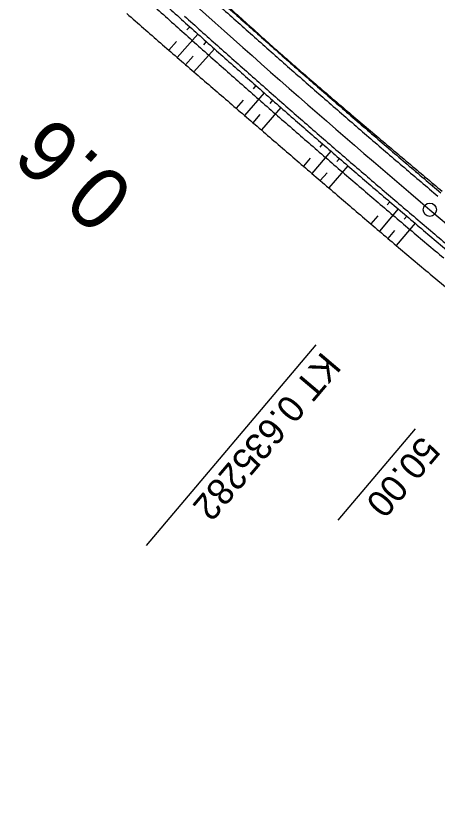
# Model space of a CAD drawing. Extents: x -481656 to -478728, y -1113199 to -1110710.
# Drawn here: x -481310.8 to -481263.1, y -1113096.8 to -1113006.1 of the extents above; entities that cross this region are included whole.
import ezdxf

# ---------------------------------------------------------------- set-up
doc = ezdxf.new("R2010")
doc.units = 0
for name, color, linetype in [('C11_HATCH_SLOPE_L', 7, 'Continuous'), ('C11_HATCH_SLOPE_R', 7, 'Continuous'), ('C11_HECTOMETRY', 7, 'Continuous'), ('C11_HLBODY', 7, 'Continuous'), ('C11_HRANA_TELESO', 7, 'Continuous'), ('C11_KORUNA', 7, 'Continuous'), ('C11_OSA', 7, 'Continuous'), ('C11_PRIKOP', 7, 'Continuous'), ('C11_STANICENI', 7, 'Continuous'), ('C11_VOZOVKA', 7, 'Continuous'), ('C11_ZPEVKRAJ', 7, 'Continuous')]:
    doc.layers.add(name, color=color, linetype=linetype)

msp = doc.modelspace()

# ---------------------------------------------------------------- linework, layer by layer
at = {"layer": 'C11_HATCH_SLOPE_L'}
for p, q in [((-481285.358, -1113006.444), (-481285.3, -1113006.378)), ((-481280.687, -1113010.579), (-481280.666, -1113010.555)), ((-481280.645, -1113010.531), (-481280.645, -1113010.531)), ((-481279.751, -1113011.403), (-481279.706, -1113011.353)), ((-481278.766, -1113012.173), (-481278.766, -1113012.173)), ((-481278.813, -1113012.226), (-481278.79, -1113012.2)), ((-481277.875, -1113013.049), (-481277.825, -1113012.992)), ((-481273.17, -1113017.145), (-481273.127, -1113017.096)), ((-481273.084, -1113017.046), (-481273.084, -1113017.046)), ((-481272.226, -1113017.962), (-481272.133, -1113017.854)), ((-481271.282, -1113018.777), (-481271.232, -1113018.718)), ((-481271.181, -1113018.66), (-481271.181, -1113018.66)), ((-481270.337, -1113019.591), (-481270.229, -1113019.466)), ((-481265.598, -1113023.648), (-481265.528, -1113023.565)), ((-481265.457, -1113023.482), (-481265.457, -1113023.482)), ((-481264.648, -1113024.457), (-481264.503, -1113024.286)), ((-481263.697, -1113025.264), (-481263.622, -1113025.176)), ((-481263.548, -1113025.089), (-481263.548, -1113025.089))]:
    msp.add_line(p, q, dxfattribs=at)
at = {"layer": 'C11_HATCH_SLOPE_R'}
for p, q in [((-481291.152, -1113007.302), (-481291.474, -1113007.662)), ((-481290.219, -1113008.138), (-481292.571, -1113010.769)), ((-481292.659, -1113008.984), (-481293.521, -1113009.947)), ((-481289.285, -1113008.972), (-481289.605, -1113009.331)), ((-481288.35, -1113009.805), (-481290.669, -1113012.41)), ((-481290.772, -1113010.64), (-481291.62, -1113011.59)), ((-481283.662, -1113013.956), (-481283.976, -1113014.312)), ((-481282.722, -1113014.783), (-481284.954, -1113017.322)), ((-481285.098, -1113015.586), (-481285.906, -1113016.503)), ((-481281.78, -1113015.609), (-481282.092, -1113015.965)), ((-481280.839, -1113016.435), (-481283.047, -1113018.958)), ((-481283.203, -1113017.231), (-481284.001, -1113018.141)), ((-481276.116, -1113020.547), (-481276.422, -1113020.9)), ((-481275.169, -1113021.366), (-481277.335, -1113023.872)), ((-481277.509, -1113022.154), (-481278.288, -1113023.055)), ((-481273.272, -1113023.002), (-481275.424, -1113025.502)), ((-481274.221, -1113022.184), (-481274.526, -1113022.537)), ((-481275.605, -1113023.788), (-481276.38, -1113024.687)), ((-481268.516, -1113027.074), (-481268.814, -1113027.424)), ((-481267.562, -1113027.886), (-481269.698, -1113030.399)), ((-481269.884, -1113028.68), (-481270.654, -1113029.585)), ((-481266.607, -1113028.696), (-481266.904, -1113029.046)), ((-481267.97, -1113030.304), (-481268.741, -1113031.212)), ((-481265.652, -1113029.506), (-481267.783, -1113032.025))]:
    msp.add_line(p, q, dxfattribs=at)
at = {"layer": 'C11_HLBODY'}
msp.add_line((-481276.899, -1113043.241), (-481296.08, -1113065.916), dxfattribs=at)
msp.add_circle((-481263.983, -1113027.971), 0.75, dxfattribs=at)
at = {"layer": 'C11_HRANA_TELESO'}
msp.add_line((-481263.952, -1113035.239), (-481260.121, -1113038.453), dxfattribs=at)
for centre, radius, start, end in [((-480481.223, -1112118.795), 1197.641, 227.587328, 227.826069), ((-480504.17, -1112098.337), 1205.863, 228.812678, 229.051444), ((-480484.126, -1112116.126), 1197.677, 228.014683, 228.253419), ((-480504.003, -1112098.593), 1205.78, 229.037497, 229.276264), ((-480491.695, -1112109.42), 1197.683, 228.737172, 228.975906), ((-480503.293, -1112099.312), 1205.698, 229.228419, 229.467183), ((-480497.095, -1112104.789), 1197.653, 229.316253, 229.554994), ((-480499.178, -1112102.936), 1205.631, 229.206586, 229.445333), ((-480497.443, -1112104.552), 1197.607, 229.575008, 229.813753), ((-480494.105, -1112107.357), 1205.589, 229.125553, 229.364289), ((-480497.596, -1112104.484), 1197.561, 229.82145, 230.060194), ((-480493.699, -1112107.742), 1205.562, 229.337739, 229.576475), ((-480493.083, -1112108.328), 1197.526, 229.776553, 230.015289), ((-480489.333, -1112111.496), 1205.548, 229.302819, 229.541553), ((-480488.495, -1112112.211), 1205.548, 229.489211, 229.727944), ((-480878.463, -1112571.843), 602.775, 229.768303, 230.2437)]:
    msp.add_arc(centre, radius, start, end, dxfattribs=at)
at = {"layer": 'C11_KORUNA'}
for centre, radius, start, end in [((-480489, -1112111.782), 1202.25, 227.849589, 228.088322), ((-480489, -1112111.782), 1197.75, 228.088322, 228.327056), ((-480489, -1112111.782), 1202.25, 228.088322, 228.327056), ((-480489, -1112111.782), 1197.75, 228.327056, 228.565789), ((-480489, -1112111.782), 1202.25, 228.327056, 228.565789), ((-480489, -1112111.782), 1197.75, 228.565786, 228.804519), ((-480489, -1112111.782), 1197.75, 228.804519, 229.043253), ((-480489, -1112111.782), 1202.25, 228.565789, 228.804522), ((-480489, -1112111.782), 1202.25, 228.804519, 229.043253), ((-480489, -1112111.782), 1197.75, 229.043253, 229.281986), ((-480489, -1112111.782), 1202.25, 229.043253, 229.281986), ((-480489, -1112111.782), 1197.75, 229.281986, 229.520719), ((-480489, -1112111.782), 1202.25, 229.281986, 229.520719), ((-480489, -1112111.782), 1197.75, 229.520719, 229.759453), ((-480489, -1112111.782), 1202.25, 229.520719, 229.759453), ((-480875.525, -1112572.174), 601.125, 229.534178, 230.0108)]:
    msp.add_arc(centre, radius, start, end, dxfattribs=at)
at = {"layer": 'C11_OSA'}
msp.add_line((-481263.983, -1113027.971), (-481182.61, -1113096.802), dxfattribs=at)
msp.add_arc((-480489, -1112111.782), 1200, 227.633469, 229.772919, dxfattribs=at)
at = {"layer": 'C11_PRIKOP'}
for centre, radius, start, end in [((-480490.048, -1112110.838), 1203.221, 227.916725, 228.155458), ((-480490.35, -1112110.577), 1203.214, 228.174467, 228.4132), ((-480490.366, -1112110.573), 1203.207, 228.4139, 228.652633), ((-480490.368, -1112110.581), 1203.199, 228.652458, 228.891192), ((-480490.376, -1112110.584), 1203.191, 228.891367, 229.1301), ((-480490.381, -1112110.59), 1203.184, 229.1301, 229.368833), ((-480490.386, -1112110.596), 1203.176, 229.368833, 229.607567), ((-480490.394, -1112110.599), 1203.169, 229.607742, 229.846475), ((-480876.516, -1112571.93), 601.582, 229.621411, 230.097692)]:
    msp.add_arc(centre, radius, start, end, dxfattribs=at)
at = {"layer": 'C11_STANICENI'}
msp.add_line((-481265.662, -1113052.746), (-481274.381, -1113063.053), dxfattribs=at)
at = {"layer": 'C11_VOZOVKA'}
for centre, radius, start, end in [((-480489, -1112111.782), 1198.25, 228.088322, 228.327056), ((-480489, -1112111.782), 1201.75, 228.088322, 228.327056), ((-480489, -1112111.782), 1198.25, 228.327056, 228.565789), ((-480489, -1112111.782), 1201.75, 228.327056, 228.565789), ((-480489, -1112111.782), 1198.25, 228.565786, 228.804519), ((-480489, -1112111.782), 1201.75, 228.565789, 228.804522), ((-480489, -1112111.782), 1198.25, 228.804519, 229.043253), ((-480489, -1112111.782), 1201.75, 228.804519, 229.043253), ((-480489, -1112111.782), 1198.25, 229.043253, 229.281986), ((-480489, -1112111.782), 1201.75, 229.043253, 229.281986), ((-480489, -1112111.782), 1198.25, 229.281986, 229.520719), ((-480489, -1112111.782), 1201.75, 229.281986, 229.520719), ((-480489, -1112111.782), 1198.25, 229.520719, 229.759453), ((-480489, -1112111.782), 1201.75, 229.520719, 229.759453), ((-480875.363, -1112571.983), 600.875, 229.534083, 230.010894)]:
    msp.add_arc(centre, radius, start, end, dxfattribs=at)
at = {"layer": 'C11_ZPEVKRAJ'}
for centre, radius, start, end in [((-480489, -1112111.782), 1198.25, 228.088322, 228.327056), ((-480489, -1112111.782), 1201.75, 228.088322, 228.327056), ((-480489, -1112111.782), 1198.25, 228.327056, 228.565789), ((-480489, -1112111.782), 1201.75, 228.327056, 228.565789), ((-480489, -1112111.782), 1198.25, 228.565786, 228.804519), ((-480489, -1112111.782), 1201.75, 228.565789, 228.804522), ((-480489, -1112111.782), 1198.25, 228.804519, 229.043253), ((-480489, -1112111.782), 1201.75, 228.804519, 229.043253), ((-480489, -1112111.782), 1198.25, 229.043253, 229.281986), ((-480489, -1112111.782), 1201.75, 229.043253, 229.281986), ((-480489, -1112111.782), 1198.25, 229.281986, 229.520719), ((-480489, -1112111.782), 1201.75, 229.281986, 229.520719), ((-480489, -1112111.782), 1198.25, 229.520719, 229.759453), ((-480489, -1112111.782), 1201.75, 229.520719, 229.759453), ((-480875.363, -1112571.983), 600.875, 229.534083, 230.010894)]:
    msp.add_arc(centre, radius, start, end, dxfattribs=at)

# ---------------------------------------------------------------- texts
at = {"layer": 'C11_HECTOMETRY'}
msp.add_text('0.6', height=6.999, rotation=138.0427, dxfattribs=at).set_placement((-481297.097, -1113025.829))
at = {"layer": 'C11_HLBODY'}
msp.add_text('KT 0.635282', height=2.999, rotation=229.77293, dxfattribs=at).set_placement((-481276.135, -1113043.886))
at = {"layer": 'C11_STANICENI'}
msp.add_text('50.00', height=3, rotation=229.77293, dxfattribs=at).set_placement((-481264.898, -1113053.391))

doc.saveas('drawing.dxf')
